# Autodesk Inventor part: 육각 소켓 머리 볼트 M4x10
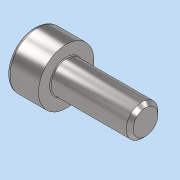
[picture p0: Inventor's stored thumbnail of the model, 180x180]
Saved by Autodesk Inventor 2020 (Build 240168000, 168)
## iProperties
Created: 2024-11
Part Number: 육각 소켓 머리 볼트 M4x10
Material: 강철, 연강
Description: 6각머리 태핑 나사
Document SubType Name: Modeling
Designer: 1강의실14
Density: 7.85 g/cm^3
Appearance: 기본값
Author: jhkim
Sending System: Autodesk Inventor 2025
Preprocessor: ST-DEVELOPER v20
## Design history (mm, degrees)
node "육각 소켓 머리 볼트 M4x101"
node "솔리드1"
body "Solid1"
